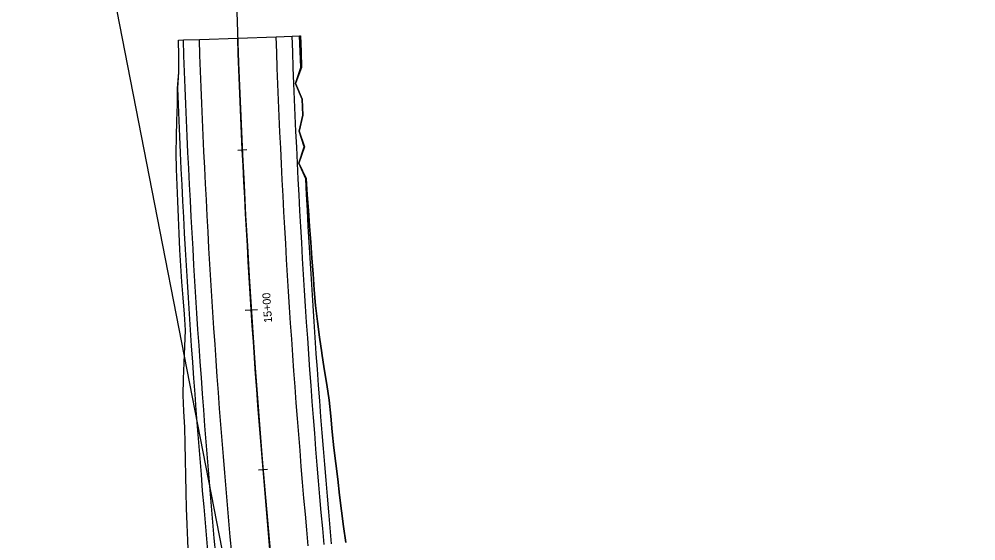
# Model space of a CAD drawing. Extents: x 1150550 to 1151113, y 1141187 to 1143500.
# Drawn here: x 1150657.5 to 1150956.3, y 1142407.3 to 1142570.1 of the extents above; entities that cross this region are included whole.
import ezdxf

# ---------------------------------------------------------------- set-up
doc = ezdxf.new("R2010")
doc.units = 0
for name, color, linetype in [('AC_P', 7, 'Continuous'), ('ACSR_P_T', 7, 'Continuous'), ('ACSRT_P', 7, 'Continuous'), ('Default', 7, 'Continuous'), ('LCUT_P', 7, 'Continuous'), ('LELB_P', 7, 'Continuous'), ('LFILL_P', 7, 'Continuous'), ('PE_P', 7, 'Continuous'), ('PET_P', 7, 'Continuous'), ('XSCTOP1_P', 7, 'Continuous')]:
    doc.layers.add(name, color=color, linetype=linetype)

msp = doc.modelspace()

# ---------------------------------------------------------------- linework, layer by layer
at = {"layer": 'AC_P'}
msp.add_lwpolyline([(1150735.81, 1142404.65), (1150735.36, 1142409.63), (1150734.92, 1142414.61), (1150734.48, 1142419.59), (1150734.06, 1142424.57), (1150733.64, 1142429.56), (1150733.24, 1142434.54), (1150732.84, 1142439.52), (1150732.45, 1142444.51), (1150732.07, 1142449.49), (1150731.7, 1142454.48), (1150731.33, 1142459.47), (1150730.99, 1142464.35), (1150730.98, 1142464.45), (1150730.63, 1142469.44), (1150730.3, 1142474.43), (1150729.97, 1142479.42), (1150729.65, 1142484.41), (1150729.34, 1142489.4), (1150729.04, 1142494.39), (1150728.75, 1142499.38), (1150728.46, 1142504.37), (1150728.19, 1142509.37), (1150727.92, 1142514.36), (1150727.67, 1142519.35), (1150727.42, 1142524.35), (1150727.18, 1142529.34), (1150726.95, 1142534.34), (1150726.73, 1142539.33), (1150726.51, 1142544.33), (1150726.31, 1142549.32), (1150726.11, 1142554.32), (1150725.93, 1142559.31), (1150725.75, 1142564.21)], dxfattribs=at)
msp.add_arc((1153549.06, 1142662.07), 2825, 166.27261, 191.05386, dxfattribs=at)
at = {"layer": 'ACSRT_P'}
for points in [[(1150725.74, 1142529.27), (1150728.62, 1142529.41)], [(1150728.05, 1142479.3), (1150731.89, 1142479.54)], [(1150732.21, 1142429.44), (1150735.08, 1142429.67)]]:
    msp.add_lwpolyline(points, dxfattribs=at)
at = {"layer": 'Default'}
msp.add_line((1150956.27, 1141200.06), (1150657.48, 1142729.55), dxfattribs=at)
at = {"layer": 'LCUT_P'}
msp.add_lwpolyline([(1150745.7, 1142555.07), (1150745.53, 1142560.03), (1150745.37, 1142564.89)], dxfattribs=at)
at = {"layer": 'LELB_P'}
for points in [[(1150710.37, 1142402.32), (1150710.14, 1142407.37), (1150709.92, 1142412.41), (1150709.76, 1142417.46), (1150709.65, 1142422.51), (1150709.54, 1142427.56), (1150709.45, 1142432.62), (1150709.37, 1142437.67), (1150709.21, 1142442.71), (1150708.93, 1142447.75), (1150708.66, 1142452.78), (1150708.78, 1142457.84), (1150708.99, 1142462.81), (1150708.99, 1142462.91), (1150709.23, 1142467.98), (1150709.47, 1142473.04), (1150709.12, 1142478.07), (1150708.7, 1142483.09), (1150708.3, 1142488.11), (1150707.94, 1142493.14), (1150707.65, 1142498.17), (1150707.42, 1142503.2), (1150707.21, 1142508.23), (1150707, 1142513.26), (1150706.79, 1142518.3), (1150706.59, 1142523.33), (1150706.52, 1142528.37), (1150706.59, 1142533.41), (1150706.72, 1142538.46), (1150706.92, 1142543.51), (1150706.97, 1142548.55), (1150707.34, 1142553.6), (1150707.39, 1142558.64), (1150707.24, 1142563.57), (1150708.76, 1142563.62), (1150713.76, 1142563.79), (1150725.75, 1142564.21), (1150737.75, 1142564.62), (1150742.74, 1142564.8), (1150745.08, 1142564.88), (1150745.37, 1142564.89), (1150745.53, 1142560.03), (1150745.7, 1142555.07), (1150743.79, 1142550.02), (1150745.84, 1142545.13), (1150746.04, 1142540.17), (1150744.97, 1142535.15), (1150746.56, 1142530.25), (1150744.84, 1142525.2), (1150747.1, 1142520.34), (1150747.47, 1142515.38), (1150747.82, 1142510.43), (1150748.17, 1142505.48), (1150748.54, 1142500.52), (1150748.93, 1142495.57), (1150749.28, 1142490.62), (1150749.65, 1142485.67), (1150750.07, 1142480.72), (1150750.69, 1142475.79), (1150751.32, 1142470.86), (1150752.03, 1142465.93), (1150752.05, 1142465.83), (1150752.77, 1142461.01), (1150753.52, 1142456.09), (1150754.28, 1142451.17), (1150754.77, 1142446.23), (1150755.23, 1142441.29), (1150755.79, 1142436.36), (1150756.37, 1142431.43), (1150756.96, 1142426.5), (1150757.56, 1142421.58), (1150758.18, 1142416.66), (1150758.81, 1142411.73), (1150759.46, 1142406.81)], [(1150755.06, 1142406.41), (1150754.62, 1142411.36), (1150754.18, 1142416.3), (1150753.75, 1142421.25), (1150753.32, 1142426.2), (1150752.91, 1142431.15), (1150752.51, 1142436.1), (1150752.11, 1142441.05), (1150751.72, 1142446), (1150751.35, 1142450.95), (1150750.98, 1142455.9), (1150750.62, 1142460.85), (1150750.27, 1142465.7), (1150750.27, 1142465.81), (1150749.92, 1142470.76), (1150749.59, 1142475.71), (1150749.26, 1142480.67), (1150748.95, 1142485.63), (1150748.64, 1142490.58), (1150748.34, 1142495.54), (1150748.05, 1142500.5), (1150747.77, 1142505.45), (1150747.49, 1142510.41), (1150747.23, 1142515.37), (1150746.97, 1142520.33), (1150744.84, 1142525.2), (1150746.49, 1142530.25), (1150744.97, 1142535.15), (1150746.04, 1142540.17), (1150745.83, 1142545.13), (1150743.79, 1142550.02), (1150745.43, 1142555.06), (1150745.25, 1142560.02), (1150745.08, 1142564.88)], [(1150716.56, 1142402.89), (1150716.1, 1142407.9), (1150715.66, 1142412.92), (1150715.22, 1142417.93), (1150714.79, 1142422.95), (1150714.38, 1142427.96), (1150713.97, 1142432.98), (1150713.57, 1142438), (1150713.17, 1142443.02), (1150712.79, 1142448.04), (1150712.42, 1142453.06), (1150712.05, 1142458.08), (1150711.7, 1142463), (1150711.69, 1142463.1), (1150711.35, 1142468.12), (1150711.01, 1142473.15), (1150710.68, 1142478.17), (1150710.36, 1142483.19), (1150710.04, 1142488.22), (1150709.74, 1142493.24), (1150709.45, 1142498.27), (1150709.16, 1142503.29), (1150708.88, 1142508.32), (1150708.62, 1142513.35), (1150708.36, 1142518.38), (1150708.11, 1142523.4), (1150707.87, 1142528.43), (1150707.63, 1142533.46), (1150707.41, 1142538.49), (1150707.2, 1142543.52), (1150706.99, 1142548.55), (1150707.34, 1142553.6), (1150707.39, 1142558.64), (1150707.24, 1142563.57)]]:
    msp.add_lwpolyline(points, dxfattribs=at)
at = {"layer": 'LFILL_P'}
for points in [[(1150710.37, 1142402.32), (1150710.14, 1142407.37), (1150709.92, 1142412.41), (1150709.76, 1142417.46), (1150709.65, 1142422.51), (1150709.54, 1142427.56), (1150709.45, 1142432.62), (1150709.37, 1142437.67), (1150709.21, 1142442.71), (1150708.93, 1142447.75), (1150708.66, 1142452.78), (1150708.78, 1142457.84), (1150708.99, 1142462.81), (1150708.99, 1142462.91), (1150709.23, 1142467.98), (1150709.47, 1142473.04), (1150709.12, 1142478.07), (1150708.7, 1142483.09), (1150708.3, 1142488.11), (1150707.94, 1142493.14), (1150707.65, 1142498.17), (1150707.42, 1142503.2), (1150707.21, 1142508.23), (1150707, 1142513.26), (1150706.79, 1142518.3), (1150706.59, 1142523.33), (1150706.52, 1142528.37), (1150706.59, 1142533.41), (1150706.72, 1142538.46), (1150706.92, 1142543.51), (1150706.97, 1142548.55)], [(1150746.04, 1142540.17), (1150745.84, 1142545.13)], [(1150759.46, 1142406.81), (1150758.81, 1142411.73), (1150758.18, 1142416.66), (1150757.56, 1142421.58), (1150756.96, 1142426.5), (1150756.37, 1142431.43), (1150755.79, 1142436.36), (1150755.23, 1142441.29), (1150754.77, 1142446.23), (1150754.28, 1142451.17), (1150753.52, 1142456.09), (1150752.77, 1142461.01), (1150752.05, 1142465.83), (1150752.03, 1142465.93), (1150751.32, 1142470.86), (1150750.69, 1142475.79), (1150750.07, 1142480.72), (1150749.65, 1142485.67), (1150749.28, 1142490.62), (1150748.93, 1142495.57), (1150748.54, 1142500.52), (1150748.17, 1142505.48), (1150747.82, 1142510.43), (1150747.47, 1142515.38), (1150747.1, 1142520.34)]]:
    msp.add_lwpolyline(points, dxfattribs=at)
at = {"layer": 'PE_P'}
for points in [[(1150752.74, 1142406.2), (1150752.29, 1142411.15), (1150751.85, 1142416.1), (1150751.42, 1142421.05), (1150751, 1142426), (1150750.59, 1142430.95), (1150750.18, 1142435.91), (1150749.79, 1142440.86), (1150749.4, 1142445.82), (1150749.02, 1142450.77), (1150748.65, 1142455.73), (1150748.29, 1142460.69), (1150747.94, 1142465.54), (1150747.94, 1142465.64), (1150747.59, 1142470.6), (1150747.26, 1142475.56), (1150746.93, 1142480.52), (1150746.62, 1142485.48), (1150746.31, 1142490.44), (1150746.01, 1142495.4), (1150745.72, 1142500.36), (1150745.44, 1142505.32), (1150745.16, 1142510.29), (1150744.9, 1142515.25), (1150744.64, 1142520.21), (1150744.4, 1142525.18), (1150744.16, 1142530.14), (1150743.93, 1142535.1), (1150743.71, 1142540.07), (1150743.5, 1142545.03), (1150743.3, 1142550), (1150743.1, 1142554.97), (1150742.92, 1142559.93), (1150742.74, 1142564.8)], [(1150718.88, 1142403.1), (1150718.43, 1142408.11), (1150717.98, 1142413.12), (1150717.55, 1142418.13), (1150717.12, 1142423.14), (1150716.7, 1142428.16), (1150716.29, 1142433.17), (1150715.89, 1142438.18), (1150715.5, 1142443.2), (1150715.12, 1142448.21), (1150714.74, 1142453.23), (1150714.38, 1142458.25), (1150714.03, 1142463.16), (1150714.02, 1142463.26), (1150713.67, 1142468.28), (1150713.33, 1142473.3), (1150713.01, 1142478.32), (1150712.68, 1142483.34), (1150712.37, 1142488.36), (1150712.07, 1142493.38), (1150711.78, 1142498.4), (1150711.49, 1142503.43), (1150711.21, 1142508.45), (1150710.95, 1142513.47), (1150710.69, 1142518.49), (1150710.44, 1142523.52), (1150710.2, 1142528.54), (1150709.97, 1142533.57), (1150709.74, 1142538.59), (1150709.53, 1142543.62), (1150709.32, 1142548.64), (1150709.13, 1142553.67), (1150708.94, 1142558.7), (1150708.76, 1142563.62)]]:
    msp.add_lwpolyline(points, dxfattribs=at)
at = {"layer": 'PET_P'}
for points in [[(1150747.76, 1142405.74), (1150747.31, 1142410.7), (1150746.87, 1142415.66), (1150746.44, 1142420.62), (1150746.02, 1142425.58), (1150745.6, 1142430.54), (1150745.2, 1142435.51), (1150744.8, 1142440.47), (1150744.41, 1142445.43), (1150744.03, 1142450.4), (1150743.66, 1142455.36), (1150743.3, 1142460.33), (1150742.96, 1142465.19), (1150742.95, 1142465.29), (1150742.61, 1142470.26), (1150742.27, 1142475.23), (1150741.94, 1142480.2), (1150741.63, 1142485.16), (1150741.32, 1142490.13), (1150741.02, 1142495.1), (1150740.73, 1142500.07), (1150740.45, 1142505.04), (1150740.17, 1142510.02), (1150739.91, 1142514.99), (1150739.65, 1142519.96), (1150739.4, 1142524.93), (1150739.17, 1142529.9), (1150738.94, 1142534.88), (1150738.72, 1142539.85), (1150738.5, 1142544.83), (1150738.3, 1142549.8), (1150738.11, 1142554.78), (1150737.92, 1142559.75), (1150737.75, 1142564.62)], [(1150723.86, 1142403.56), (1150723.41, 1142408.56), (1150722.96, 1142413.56), (1150722.53, 1142418.56), (1150722.1, 1142423.56), (1150721.68, 1142428.57), (1150721.28, 1142433.57), (1150720.88, 1142438.58), (1150720.48, 1142443.58), (1150720.1, 1142448.59), (1150719.73, 1142453.6), (1150719.36, 1142458.61), (1150719.02, 1142463.51), (1150719.01, 1142463.61), (1150718.66, 1142468.62), (1150718.32, 1142473.63), (1150717.99, 1142478.64), (1150717.67, 1142483.65), (1150717.36, 1142488.67), (1150717.06, 1142493.68), (1150716.77, 1142498.69), (1150716.48, 1142503.7), (1150716.21, 1142508.72), (1150715.94, 1142513.73), (1150715.68, 1142518.75), (1150715.43, 1142523.76), (1150715.19, 1142528.78), (1150714.96, 1142533.79), (1150714.74, 1142538.81), (1150714.52, 1142543.83), (1150714.32, 1142548.84), (1150714.12, 1142553.86), (1150713.94, 1142558.88), (1150713.76, 1142563.79)]]:
    msp.add_lwpolyline(points, dxfattribs=at)
at = {"layer": 'XSCTOP1_P'}
for points in [[(1150735.81, 1142404.65), (1150735.36, 1142409.63), (1150734.92, 1142414.61), (1150734.48, 1142419.59), (1150734.06, 1142424.57), (1150733.64, 1142429.56), (1150733.24, 1142434.54), (1150732.84, 1142439.52), (1150732.45, 1142444.51), (1150732.07, 1142449.49), (1150731.7, 1142454.48), (1150731.33, 1142459.47), (1150730.99, 1142464.35), (1150730.98, 1142464.45), (1150730.63, 1142469.44), (1150730.3, 1142474.43), (1150729.97, 1142479.42), (1150729.65, 1142484.41), (1150729.34, 1142489.4), (1150729.04, 1142494.39), (1150728.75, 1142499.38), (1150728.46, 1142504.37), (1150728.19, 1142509.37), (1150727.92, 1142514.36), (1150727.67, 1142519.35), (1150727.42, 1142524.35), (1150727.18, 1142529.34), (1150726.95, 1142534.34), (1150726.73, 1142539.33), (1150726.51, 1142544.33), (1150726.31, 1142549.32), (1150726.11, 1142554.32), (1150725.93, 1142559.31), (1150725.75, 1142564.21)], [(1150747.76, 1142405.74), (1150747.31, 1142410.7), (1150746.87, 1142415.66), (1150746.44, 1142420.62), (1150746.02, 1142425.58), (1150745.6, 1142430.54), (1150745.2, 1142435.51), (1150744.8, 1142440.47), (1150744.41, 1142445.43), (1150744.03, 1142450.4), (1150743.66, 1142455.36), (1150743.3, 1142460.33), (1150742.96, 1142465.19), (1150742.95, 1142465.29), (1150742.61, 1142470.26), (1150742.27, 1142475.23), (1150741.94, 1142480.2), (1150741.63, 1142485.16), (1150741.32, 1142490.13), (1150741.02, 1142495.1), (1150740.73, 1142500.07), (1150740.45, 1142505.04), (1150740.17, 1142510.02), (1150739.91, 1142514.99), (1150739.65, 1142519.96), (1150739.4, 1142524.93), (1150739.17, 1142529.9), (1150738.94, 1142534.88), (1150738.72, 1142539.85), (1150738.5, 1142544.83), (1150738.3, 1142549.8), (1150738.11, 1142554.78), (1150737.92, 1142559.75), (1150737.75, 1142564.62)], [(1150752.74, 1142406.2), (1150752.29, 1142411.15), (1150751.85, 1142416.1), (1150751.42, 1142421.05), (1150751, 1142426), (1150750.59, 1142430.95), (1150750.18, 1142435.91), (1150749.79, 1142440.86), (1150749.4, 1142445.82), (1150749.02, 1142450.77), (1150748.65, 1142455.73), (1150748.29, 1142460.69), (1150747.94, 1142465.54), (1150747.94, 1142465.64), (1150747.59, 1142470.6), (1150747.26, 1142475.56), (1150746.93, 1142480.52), (1150746.62, 1142485.48), (1150746.31, 1142490.44), (1150746.01, 1142495.4), (1150745.72, 1142500.36), (1150745.44, 1142505.32), (1150745.16, 1142510.29), (1150744.9, 1142515.25), (1150744.64, 1142520.21), (1150744.4, 1142525.18), (1150744.16, 1142530.14), (1150743.93, 1142535.1), (1150743.71, 1142540.07), (1150743.5, 1142545.03), (1150743.3, 1142550), (1150743.1, 1142554.97), (1150742.92, 1142559.93), (1150742.74, 1142564.8)], [(1150718.88, 1142403.1), (1150718.43, 1142408.11), (1150717.98, 1142413.12), (1150717.55, 1142418.13), (1150717.12, 1142423.14), (1150716.7, 1142428.16), (1150716.29, 1142433.17), (1150715.89, 1142438.18), (1150715.5, 1142443.2), (1150715.12, 1142448.21), (1150714.74, 1142453.23), (1150714.38, 1142458.25), (1150714.03, 1142463.16), (1150714.02, 1142463.26), (1150713.67, 1142468.28), (1150713.33, 1142473.3), (1150713.01, 1142478.32), (1150712.68, 1142483.34), (1150712.37, 1142488.36), (1150712.07, 1142493.38), (1150711.78, 1142498.4), (1150711.49, 1142503.43), (1150711.21, 1142508.45), (1150710.95, 1142513.47), (1150710.69, 1142518.49), (1150710.44, 1142523.52), (1150710.2, 1142528.54), (1150709.97, 1142533.57), (1150709.74, 1142538.59), (1150709.53, 1142543.62), (1150709.32, 1142548.64), (1150709.13, 1142553.67), (1150708.94, 1142558.7), (1150708.76, 1142563.62)], [(1150723.86, 1142403.56), (1150723.41, 1142408.56), (1150722.96, 1142413.56), (1150722.53, 1142418.56), (1150722.1, 1142423.56), (1150721.68, 1142428.57), (1150721.28, 1142433.57), (1150720.88, 1142438.58), (1150720.48, 1142443.58), (1150720.1, 1142448.59), (1150719.73, 1142453.6), (1150719.36, 1142458.61), (1150719.02, 1142463.51), (1150719.01, 1142463.61), (1150718.66, 1142468.62), (1150718.32, 1142473.63), (1150717.99, 1142478.64), (1150717.67, 1142483.65), (1150717.36, 1142488.67), (1150717.06, 1142493.68), (1150716.77, 1142498.69), (1150716.48, 1142503.7), (1150716.21, 1142508.72), (1150715.94, 1142513.73), (1150715.68, 1142518.75), (1150715.43, 1142523.76), (1150715.19, 1142528.78), (1150714.96, 1142533.79), (1150714.74, 1142538.81), (1150714.52, 1142543.83), (1150714.32, 1142548.84), (1150714.12, 1142553.86), (1150713.94, 1142558.88), (1150713.76, 1142563.79)]]:
    msp.add_lwpolyline(points, dxfattribs=at)

# ---------------------------------------------------------------- texts
at = {"layer": 'ACSR_P_T'}
msp.add_text('15+00', height=2.501, rotation=93.7071, dxfattribs=at).set_placement((1150736.49, 1142475.43))

doc.saveas('drawing.dxf')
